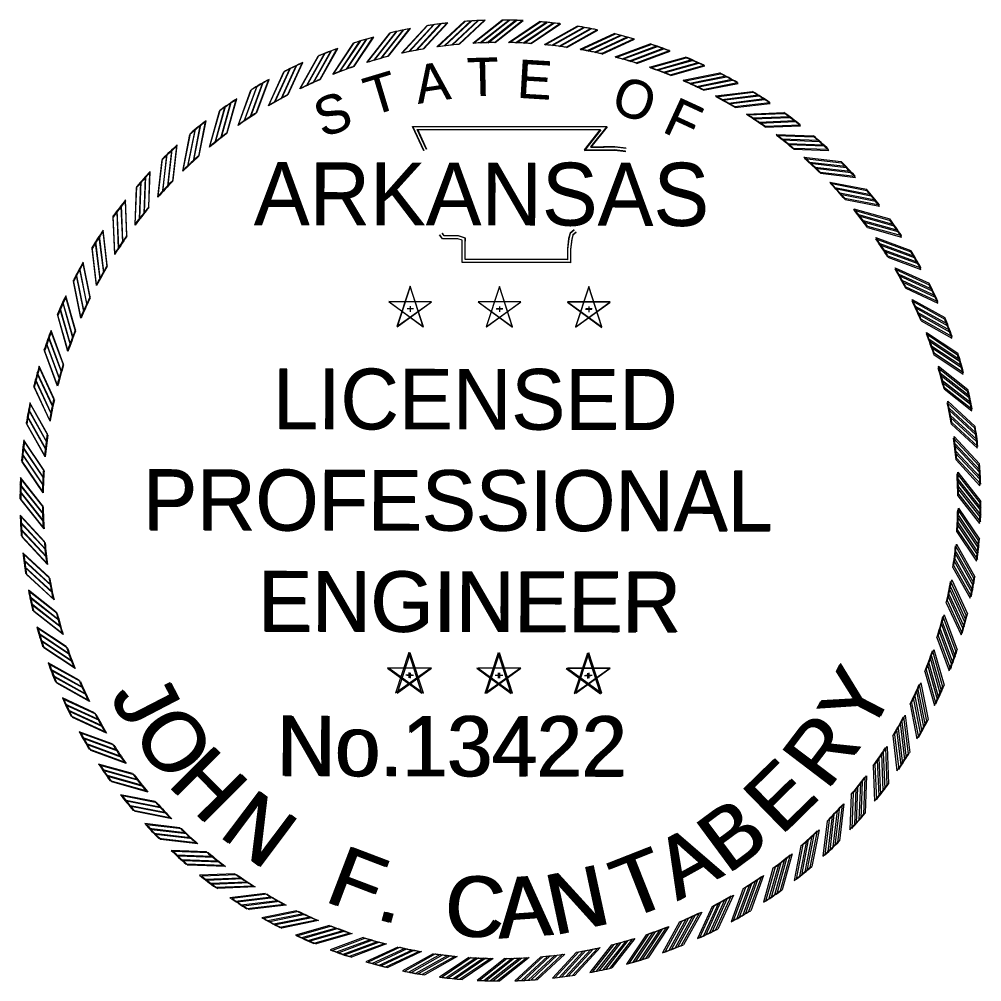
# Model space of a CAD drawing. Extents: x 1127717 to 1741049, y 2026793 to 2244711.
# Drawn here: x 1378362 to 1390517, y 2058368 to 2070515 of the extents above; entities that cross this region are included whole.
import ezdxf

# ---------------------------------------------------------------- set-up
doc = ezdxf.new("R2010")
doc.units = 0
doc.layers.add('Default', color=7, linetype='Continuous')

# ---------------------------------------------------------------- blocks, each defined once
blk = doc.blocks.new('STAR')
at = {"layer": 'Default'}
for p, q in [((-0.0001, 0.0615), (-0.0366, -0.0504)), ((0.0362, -0.0503), (0, 0.0617)), ((0.0587, 0.0188), (-0.059, 0.0189)), ((-0.0589, 0.0188), (0.0363, -0.0505)), ((-0.0365, -0.0503), (0.0589, 0.0188)), ((-0.0085, 0), (0.009, 0)), ((0, 0.0063), (0, -0.0085))]:
    blk.add_line(p, q, dxfattribs=at)
blk = doc.blocks.new('RP')
at = {"layer": 'Default'}
for p, q in [((-0.0781, 1.2656), (0.003, 1.33)), ((-0.058, 1.2667), (0.0216, 1.3299)), ((-0.0375, 1.2674), (0.0405, 1.3294)), ((-0.0176, 1.2679), (0.059, 1.3287))]:
    blk.add_line(p, q, dxfattribs=at)
for radius, start, end in [(1.33, 87.4562, 89.8699), (1.268, 90.7933, 93.5307)]:
    blk.add_arc((0, 0), radius, start, end, dxfattribs=at)

msp = doc.modelspace()

# ---------------------------------------------------------------- linework, layer by layer
at = {"layer": 'Default'}
for points in [[(1383470, 2068854), (1383329, 2069161), (1385781, 2069163), (1385576, 2068905), (1385742, 2068907), (1385882, 2068909), (1386021, 2068894)], [(1383475, 2068856), (1383334, 2069163), (1385787, 2069156), (1385581, 2068900), (1385747, 2068901), (1385887, 2068903), (1386025, 2068887)], [(1383506, 2068871), (1383389, 2069122), (1385700, 2069124), (1385494, 2068865), (1385743, 2068869), (1385880, 2068870), (1386016, 2068856)], [(1383510, 2068872), (1383395, 2069124), (1385706, 2069118), (1385499, 2068860), (1385748, 2068862), (1385885, 2068864), (1386021, 2068848)], [(1385394, 2067827), (1385352, 2067793), (1385339, 2067742), (1385325, 2067615), (1385325, 2067445), (1383956, 2067445), (1383956, 2067674), (1383956, 2067725), (1383900, 2067742), (1383706, 2067742), (1383671, 2067795)], [(1385370, 2067857), (1385318, 2067815), (1385300, 2067749), (1385286, 2067617), (1385286, 2067484), (1383995, 2067484), (1383995, 2067674), (1383995, 2067754), (1383906, 2067781), (1383727, 2067781), (1383704, 2067816)], [(1385371, 2067852), (1385320, 2067810), (1385301, 2067745), (1385286, 2067612), (1385286, 2067480), (1383995, 2067484), (1383995, 2067674), (1383996, 2067754), (1383907, 2067781), (1383728, 2067782), (1383705, 2067817)], [(1385396, 2067822), (1385354, 2067788), (1385340, 2067737), (1385325, 2067610), (1385325, 2067441), (1383956, 2067445), (1383957, 2067674), (1383957, 2067725), (1383901, 2067742), (1383707, 2067743), (1383672, 2067796)]]:
    msp.add_lwpolyline(points, dxfattribs=at)

# ---------------------------------------------------------------- block references
for name, p, xscale, yscale, rotation in [('RP', (1384444, 2064442), 4558.827671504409, 4558.827671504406, 4.500000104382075), ('RP', (1384434, 2064441), 4558.8276715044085, 4558.827671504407, 4.304199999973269), ('RP', (1384444, 2064442), 4558.8276715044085, 4558.827671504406, 1.0438208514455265e-07), ('RP', (1384434, 2064441), 4558.827671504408, 4558.827671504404, -0.19580000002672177), ('RP', (1384444, 2064442), 4558.8276715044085, 4558.827671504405, -4.499999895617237), ('RP', (1384434, 2064441), 4558.827671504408, 4558.827671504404, -4.695800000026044), ('RP', (1384444, 2064442), 4558.827671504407, 4558.827671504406, 13.500000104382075), ('RP', (1384434, 2064441), 4558.827671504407, 4558.827671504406, 13.304199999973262), ('RP', (1384444, 2064442), 4558.827671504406, 4558.827671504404, 9.000000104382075), ('RP', (1384434, 2064441), 4558.827671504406, 4558.827671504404, 8.804199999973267), ('RP', (1384444, 2064442), 4558.8276715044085, 4558.827671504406, -8.999999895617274), ('RP', (1384434, 2064441), 4558.827671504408, 4558.827671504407, -9.195800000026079), ('RP', (1384444, 2064442), 4558.827671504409, 4558.827671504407, -13.499999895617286), ('RP', (1384434, 2064441), 4558.827671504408, 4558.827671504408, -13.695800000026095), ('RP', (1384444, 2064442), 4558.8276715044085, 4558.827671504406, 18.00000010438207), ('RP', (1384434, 2064441), 4558.827671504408, 4558.827671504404, 17.80419999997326), ('RP', (1384444, 2064442), 4558.8276715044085, 4558.827671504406, -17.99999989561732), ('RP', (1384434, 2064441), 4558.827671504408, 4558.827671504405, -18.195800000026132), ('RP', (1384444, 2064442), 4558.827671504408, 4558.827671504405, 22.500000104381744), ('RP', (1384434, 2064441), 4558.827671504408, 4558.827671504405, 22.304199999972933), ('RP', (1384444, 2064442), 4558.827671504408, 4558.827671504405, -22.499999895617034), ('RP', (1384434, 2064441), 4558.827671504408, 4558.827671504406, -22.695800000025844), ('RP', (1384444, 2064442), 4558.827671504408, 4558.827671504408, 27.000000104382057), ('RP', (1384434, 2064441), 4558.827671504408, 4558.827671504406, 26.80419999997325), ('RP', (1384444, 2064442), 4558.827671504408, 4558.827671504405, -26.999999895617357), ('RP', (1384434, 2064441), 4558.827671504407, 4558.827671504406, -27.195800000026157), ('RP', (1384444, 2064442), 4558.827671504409, 4558.8276715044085, -31.49999989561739), ('RP', (1384434, 2064441), 4558.8276715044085, 4558.8276715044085, -31.695800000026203), ('RP', (1384444, 2064442), 4558.827671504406, 4558.827671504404, 31.50000010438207), ('RP', (1384434, 2064441), 4558.827671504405, 4558.827671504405, 31.30419999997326), ('RP', (1384444, 2064442), 4558.8276715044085, 4558.827671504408, -35.99999989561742), ('RP', (1384434, 2064441), 4558.827671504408, 4558.827671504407, -36.19580000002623), ('RP', (1384444, 2064442), 4558.827671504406, 4558.827671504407, 36.000000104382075), ('RP', (1384434, 2064441), 4558.827671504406, 4558.827671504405, 35.804199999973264), ('RP', (1384444, 2064442), 4558.827671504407, 4558.827671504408, -40.49999989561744), ('RP', (1384444, 2064442), 4558.827671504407, 4558.827671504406, 40.50000010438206), ('RP', (1384434, 2064441), 4558.827671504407, 4558.827671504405, 40.30419999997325), ('RP', (1384434, 2064441), 4558.827671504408, 4558.827671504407, -40.69580000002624), ('RP', (1384444, 2064442), 4558.827671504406, 4558.827671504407, 45.00000010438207), ('RP', (1384434, 2064441), 4558.827671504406, 4558.827671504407, 44.80419999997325), ('RP', (1384444, 2064442), 4558.827671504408, 4558.827671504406, -44.99999989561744), ('RP', (1384434, 2064441), 4558.827671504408, 4558.827671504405, -45.19580000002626), ('RP', (1384444, 2064442), 4558.8276715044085, 4558.827671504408, 49.50000010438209), ('RP', (1384434, 2064441), 4558.827671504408, 4558.8276715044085, 49.304199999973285), ('RP', (1384444, 2064442), 4558.827671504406, 4558.827671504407, -49.499999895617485), ('RP', (1384434, 2064441), 4558.827671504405, 4558.827671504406, -49.69580000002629), ('RP', (1384444, 2064442), 4558.827671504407, 4558.827671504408, 54.00000010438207), ('RP', (1384434, 2064441), 4558.827671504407, 4558.827671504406, 53.80419999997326), ('RP', (1384444, 2064442), 4558.827671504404, 4558.827671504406, -53.999999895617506), ('RP', (1384434, 2064441), 4558.827671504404, 4558.827671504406, -54.1958000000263), ('RP', (1384434, 2064441), 4558.827671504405, 4558.827671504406, 58.304199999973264), ('RP', (1384444, 2064442), 4558.827671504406, 4558.827671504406, 58.50000010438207), ('RP', (1384444, 2064442), 4558.827671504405, 4558.827671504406, -58.49999989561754), ('RP', (1384434, 2064441), 4558.827671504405, 4558.827671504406, -58.69580000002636), ('RP', (1384444, 2064442), 4558.827671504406, 4558.827671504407, -62.99999989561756), ('RP', (1384434, 2064441), 4558.827671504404, 4558.827671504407, -63.19580000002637), ('RP', (1384434, 2064441), 4558.827671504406, 4558.8276715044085, 62.804199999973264), ('RP', (1384444, 2064442), 4558.827671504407, 4558.8276715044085, 63.000000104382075), ('STAR', (1383298, 2066865), 4558.827671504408, 4558.827671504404, -0.19580000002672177), ('STAR', (1383300, 2066863), 4558.8276715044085, 4558.827671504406, 1.0438208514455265e-07), ('STAR', (1384425, 2066861), 4558.827671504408, 4558.827671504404, -0.19580000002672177), ('STAR', (1384427, 2066863), 4558.8276715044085, 4558.827671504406, 1.0438208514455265e-07), ('STAR', (1385553, 2066857), 4558.827671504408, 4558.827671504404, -0.19580000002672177), ('STAR', (1385555, 2066863), 4558.8276715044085, 4558.827671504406, 1.0438208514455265e-07), ('RP', (1384434, 2064441), 4558.827671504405, 4558.827671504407, 67.30419999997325), ('RP', (1384444, 2064442), 4558.827671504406, 4558.827671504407, 67.50000010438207), ('RP', (1384434, 2064441), 4558.827671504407, 4558.827671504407, -67.69580000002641), ('RP', (1384444, 2064442), 4558.827671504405, 4558.827671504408, -67.49999989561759), ('RP', (1384434, 2064441), 4558.827671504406, 4558.827671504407, -72.19580000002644), ('RP', (1384444, 2064442), 4558.827671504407, 4558.827671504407, -71.99999989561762), ('RP', (1384434, 2064441), 4558.827671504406, 4558.8276715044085, 71.80419999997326), ('RP', (1384444, 2064442), 4558.827671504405, 4558.8276715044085, 72.00000010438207), ('RP', (1384434, 2064441), 4558.827671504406, 4558.8276715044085, 76.30419999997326), ('RP', (1384434, 2064441), 4558.827671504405, 4558.827671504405, -76.69580000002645), ('RP', (1384444, 2064442), 4558.827671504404, 4558.827671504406, -76.49999989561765), ('RP', (1384444, 2064442), 4558.827671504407, 4558.8276715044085, 76.50000010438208), ('RP', (1384434, 2064441), 4558.827671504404, 4558.827671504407, 80.80419999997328), ('RP', (1384444, 2064442), 4558.827671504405, 4558.827671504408, 81.0000001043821), ('RP', (1384434, 2064441), 4558.827671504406, 4558.827671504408, -81.19580000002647), ('RP', (1384444, 2064442), 4558.827671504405, 4558.827671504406, -80.99999989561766), ('RP', (1384444, 2064442), 4558.827671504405, 4558.827671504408, -85.49999989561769), ('RP', (1384434, 2064441), 4558.827671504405, 4558.827671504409, 85.30419999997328), ('RP', (1384444, 2064442), 4558.827671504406, 4558.8276715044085, 85.50000010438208), ('RP', (1384434, 2064441), 4558.827671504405, 4558.827671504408, -85.69580000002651), ('RP', (1384444, 2064442), 4558.827671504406, 4558.8276715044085, -89.99999989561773), ('RP', (1384434, 2064441), 4558.827671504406, 4558.8276715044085, 89.80419999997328), ('RP', (1384444, 2064442), 4558.827671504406, 4558.8276715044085, 90.0000001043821), ('RP', (1384434, 2064441), 4558.827671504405, 4558.8276715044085, -90.19580000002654), ('RP', (1384434, 2064441), 4558.827671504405, 4558.8276715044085, -94.69580000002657), ('RP', (1384444, 2064442), 4558.827671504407, 4558.827671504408, -94.49999989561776), ('RP', (1384434, 2064441), 4558.827671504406, 4558.82767150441, 94.30419999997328), ('RP', (1384444, 2064442), 4558.827671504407, 4558.82767150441, 94.5000001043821), ('RP', (1384434, 2064441), 4558.827671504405, 4558.827671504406, 98.8041999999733), ('RP', (1384434, 2064441), 4558.827671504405, 4558.827671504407, -99.19580000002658), ('RP', (1384444, 2064442), 4558.827671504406, 4558.8276715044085, -98.99999989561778), ('RP', (1384444, 2064442), 4558.827671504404, 4558.827671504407, 99.0000001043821), ('RP', (1384434, 2064441), 4558.827671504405, 4558.827671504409, 103.30419999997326), ('RP', (1384444, 2064442), 4558.827671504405, 4558.8276715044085, 103.50000010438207), ('RP', (1384434, 2064441), 4558.827671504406, 4558.827671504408, -103.69580000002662), ('RP', (1384444, 2064442), 4558.827671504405, 4558.8276715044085, -103.49999989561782), ('RP', (1384434, 2064441), 4558.827671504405, 4558.827671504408, -108.19580000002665), ('RP', (1384444, 2064442), 4558.827671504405, 4558.827671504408, -107.99999989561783), ('RP', (1384434, 2064441), 4558.827671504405, 4558.82767150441, 107.80419999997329), ('RP', (1384444, 2064442), 4558.827671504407, 4558.827671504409, 108.0000001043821), ('RP', (1384434, 2064441), 4558.827671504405, 4558.827671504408, 112.30419999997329), ('RP', (1384444, 2064442), 4558.827671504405, 4558.827671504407, 112.5000001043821), ('STAR', (1383282, 2062241), 4558.827671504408, 4558.827671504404, -0.19580000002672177), ('STAR', (1383300, 2062239), 4558.8276715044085, 4558.827671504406, 1.0438208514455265e-07), ('STAR', (1384410, 2062237), 4558.827671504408, 4558.827671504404, -0.19580000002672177), ('STAR', (1384427, 2062239), 4558.8276715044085, 4558.827671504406, 1.0438208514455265e-07), ('STAR', (1385537, 2062234), 4558.827671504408, 4558.827671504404, -0.19580000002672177), ('STAR', (1385555, 2062239), 4558.8276715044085, 4558.827671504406, 1.0438208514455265e-07), ('RP', (1384434, 2064441), 4558.827671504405, 4558.827671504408, -112.69580000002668), ('RP', (1384444, 2064442), 4558.827671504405, 4558.8276715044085, -112.49999989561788), ('RP', (1384434, 2064441), 4558.827671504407, 4558.827671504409, -117.19580000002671), ('RP', (1384444, 2064442), 4558.827671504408, 4558.8276715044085, -116.9999998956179), ('RP', (1384434, 2064441), 4558.827671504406, 4558.827671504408, 116.80419999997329), ('RP', (1384444, 2064442), 4558.827671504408, 4558.827671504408, 117.0000001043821), ('RP', (1384434, 2064441), 4558.827671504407, 4558.827671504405, 121.30419999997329), ('RP', (1384444, 2064442), 4558.827671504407, 4558.827671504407, 121.5000001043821), ('RP', (1384434, 2064441), 4558.827671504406, 4558.8276715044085, -121.69580000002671), ('RP', (1384444, 2064442), 4558.827671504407, 4558.8276715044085, -121.4999998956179), ('RP', (1384434, 2064441), 4558.827671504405, 4558.827671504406, 125.80419999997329), ('RP', (1384444, 2064442), 4558.827671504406, 4558.827671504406, 126.00000010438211), ('RP', (1384434, 2064441), 4558.827671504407, 4558.827671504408, -126.19580000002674), ('RP', (1384444, 2064442), 4558.827671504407, 4558.827671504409, -125.99999989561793), ('RP', (1384434, 2064441), 4558.827671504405, 4558.827671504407, 130.3041999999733), ('RP', (1384444, 2064442), 4558.827671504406, 4558.827671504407, 130.50000010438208), ('RP', (1384434, 2064441), 4558.827671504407, 4558.827671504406, -130.6958000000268), ('RP', (1384444, 2064442), 4558.827671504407, 4558.827671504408, -130.49999989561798), ('RP', (1384434, 2064441), 4558.827671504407, 4558.827671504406, 134.8041999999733), ('RP', (1384444, 2064442), 4558.827671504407, 4558.827671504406, 135.0000001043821), ('RP', (1384434, 2064441), 4558.827671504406, 4558.827671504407, -135.19580000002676), ('RP', (1384444, 2064442), 4558.827671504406, 4558.827671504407, -134.99999989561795), ('RP', (1384434, 2064441), 4558.827671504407, 4558.827671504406, 139.30419999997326), ('RP', (1384444, 2064442), 4558.827671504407, 4558.827671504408, 139.50000010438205), ('RP', (1384434, 2064441), 4558.827671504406, 4558.827671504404, -139.69580000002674), ('RP', (1384444, 2064442), 4558.827671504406, 4558.827671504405, -139.49999989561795), ('RP', (1384434, 2064441), 4558.8276715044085, 4558.827671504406, 143.8041999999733), ('RP', (1384444, 2064442), 4558.8276715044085, 4558.827671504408, 144.00000010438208), ('RP', (1384434, 2064441), 4558.827671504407, 4558.827671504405, -144.19580000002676), ('RP', (1384444, 2064442), 4558.827671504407, 4558.827671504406, -143.99999989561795), ('RP', (1384434, 2064441), 4558.827671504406, 4558.827671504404, -148.69580000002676), ('RP', (1384444, 2064442), 4558.827671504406, 4558.827671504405, -148.49999989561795), ('RP', (1384434, 2064441), 4558.827671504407, 4558.827671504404, 148.3041999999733), ('RP', (1384444, 2064442), 4558.827671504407, 4558.827671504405, 148.50000010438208), ('RP', (1384434, 2064441), 4558.827671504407, 4558.827671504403, -153.1958000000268), ('RP', (1384444, 2064442), 4558.827671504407, 4558.827671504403, -152.99999989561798), ('RP', (1384434, 2064441), 4558.8276715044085, 4558.827671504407, 152.8041999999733), ('RP', (1384444, 2064442), 4558.82767150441, 4558.827671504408, 153.00000010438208), ('RP', (1384434, 2064441), 4558.827671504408, 4558.827671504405, 157.3041999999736), ('RP', (1384444, 2064442), 4558.827671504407, 4558.827671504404, 157.50000010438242), ('RP', (1384434, 2064441), 4558.827671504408, 4558.827671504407, -157.6958000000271), ('RP', (1384444, 2064442), 4558.827671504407, 4558.827671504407, -157.4999998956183), ('RP', (1384434, 2064441), 4558.827671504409, 4558.827671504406, 161.8041999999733), ('RP', (1384444, 2064442), 4558.827671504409, 4558.827671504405, 162.00000010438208), ('RP', (1384434, 2064441), 4558.827671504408, 4558.827671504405, -162.19580000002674), ('RP', (1384444, 2064442), 4558.8276715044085, 4558.827671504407, -161.99999989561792), ('RP', (1384434, 2064441), 4558.8276715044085, 4558.827671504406, 166.3041999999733), ('RP', (1384444, 2064442), 4558.8276715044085, 4558.827671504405, 166.50000010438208), ('RP', (1384434, 2064441), 4558.827671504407, 4558.827671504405, -166.69580000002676), ('RP', (1384444, 2064442), 4558.827671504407, 4558.827671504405, -166.49999989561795), ('RP', (1384434, 2064441), 4558.827671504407, 4558.827671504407, 170.8041999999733), ('RP', (1384444, 2064442), 4558.827671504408, 4558.827671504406, 171.00000010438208), ('RP', (1384434, 2064441), 4558.827671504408, 4558.827671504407, 175.3041999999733), ('RP', (1384444, 2064442), 4558.827671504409, 4558.827671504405, 175.50000010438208), ('RP', (1384434, 2064441), 4558.827671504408, 4558.827671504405, -175.69580000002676), ('RP', (1384444, 2064442), 4558.827671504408, 4558.827671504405, -175.49999989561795), ('RP', (1384434, 2064441), 4558.827671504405, 4558.827671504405, -171.19580000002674), ('RP', (1384444, 2064442), 4558.827671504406, 4558.827671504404, -170.99999989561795), ('RP', (1384434, 2064441), 4558.8276715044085, 4558.827671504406, 179.8041999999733), ('RP', (1384444, 2064442), 4558.8276715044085, 4558.827671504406, -179.99999989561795)]:
    msp.add_blockref(name, p, dxfattribs=dict(at, xscale=xscale, yscale=yscale, rotation=rotation))

# ---------------------------------------------------------------- texts
for s, height, rotation, p in [('T', 484, 1.4789, (1384020, 2069541)), ('T', 484, 1.2831, (1384027, 2069541)), ('A', 484, 8.6788, (1383396, 2069445)), ('A', 484, 8.483, (1383402, 2069447)), ('E', 484, 356.672, (1384639, 2069526)), ('E', 484, 356.4762, (1384646, 2069524)), ('T', 484, 16.9015, (1382808, 2069291)), ('T', 484, 16.7057, (1382815, 2069295)), ('O', 484, 341.2218, (1385814, 2069360)), ('O', 484, 341.026, (1385820, 2069354)), ('S', 484, 19.7726, (1382193, 2069015)), ('S', 484, 19.5768, (1382199, 2069021)), ('F', 484, 335.3628, (1386466, 2069105)), ('F', 484, 335.167, (1386471, 2069097)), ('ARKANSAS', 789.4, 359.8042, (1381326, 2067924)), ('LICENSED', 764.2, 359.8042, (1381562, 2065346)), ('PROFESSIONAL', 764.24, 359.8042, (1379920, 2064074)), ('ENGINEER', 764.2, 359.8042, (1381371, 2062791)), ('Y', 764, 62.5392, (1389093, 2061441)), ('Y', 764, 62.735, (1389113, 2061459)), ('J', 764, 297.2813, (1379494, 2061984)), ('J', 764, 297.4771, (1379513, 2061969)), ('O', 764, 304.1899, (1379765, 2061515)), ('O', 764, 304.3857, (1379785, 2061501)), ('No.13422', 761.2, 359.8042, (1381606, 2060968)), ('R', 764, 52.7437, (1388559, 2060768)), ('R', 764, 52.9395, (1388582, 2060784)), ('H', 764, 314.7447, (1380216, 2060857)), ('H', 764, 314.9405, (1380238, 2060844)), ('E', 764, 44.306, (1387977, 2060199)), ('E', 764, 44.5018, (1388002, 2060213)), ('N', 764, 322.9417, (1380861, 2060218)), ('N', 764, 323.1375, (1380885, 2060208)), ('B', 764, 36.505, (1387303, 2059713)), ('B', 764, 36.7008, (1387329, 2059724)), ('A', 764, 28.8562, (1386668, 2059380)), ('A', 764, 29.052, (1386695, 2059389)), ('F', 764, 339.0288, (1382195, 2059390)), ('F', 764, 339.2246, (1382222, 2059384)), ('T', 764, 21.4329, (1386033, 2059140)), ('T', 764, 21.6287, (1386061, 2059148)), ('N', 764, 12.0703, (1385111, 2058950)), ('N', 764, 12.2661, (1385140, 2058954)), ('C', 764, 356.1028, (1383711, 2058961)), ('C', 764, 356.2986, (1383740, 2058961)), ('A', 764, 3.9092, (1384412, 2058911)), ('A', 764, 4.105, (1384441, 2058912)), ('.', 764, 344.7037, (1382847, 2059164)), ('.', 764, 344.8995, (1382875, 2059161))]:
    msp.add_text(s, height=height, rotation=rotation, dxfattribs=at).set_placement(p)
for s, height, p in [('ARKANSAS', 789.4, (1381324, 2067915)), ('LICENSED', 764.2, (1381569, 2065338)), ('PROFESSIONAL', 764.24, (1379932, 2064060)), ('ENGINEER', 764.2, (1381387, 2062782)), ('No.13422', 761.2, (1381629, 2060960))]:
    msp.add_text(s, height=height, dxfattribs=at).set_placement(p)

doc.saveas('drawing.dxf')
